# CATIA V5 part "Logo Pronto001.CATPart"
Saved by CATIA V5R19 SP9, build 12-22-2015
Part number: Logo Pronto001
Definition: design
Nomenclature: Logo Pronto001
Source: Unknown
Bounding box of the stored display mesh (mm): x -12.664 to 12.648, y 51.736 to 57.613, z 35 to 36
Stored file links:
  Z:\charly_robot\Logo Pronto001.CATPart
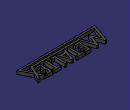
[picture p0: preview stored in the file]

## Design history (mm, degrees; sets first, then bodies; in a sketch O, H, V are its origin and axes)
AxisSystem1: origin (0, 0, 0), X (1, 0, 0), Y (0, 1, 0), Z (0, 0, 1)
Body1 "MANIFOLD_SOLID_BREP #239880" (main body)
  Solid1: solid without history
Body2 "MANIFOLD_SOLID_BREP #240450"
  Solid2: solid without history
Body3 "MANIFOLD_SOLID_BREP #241296"
  Solid3: solid without history
Body4 "MANIFOLD_SOLID_BREP #243043"
  Solid4: solid without history
Body5 "MANIFOLD_SOLID_BREP #243889"
  Solid5: solid without history
Body6 "MANIFOLD_SOLID_BREP #244670"
  Solid6: solid without history
Body7 "MANIFOLD_SOLID_BREP #245240"
  Solid7: solid without history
